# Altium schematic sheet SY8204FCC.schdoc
size 127 x 101 mm
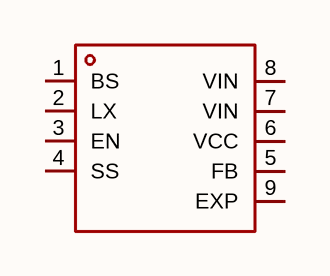
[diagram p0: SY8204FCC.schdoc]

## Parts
U?  sy8204fcc  [SOIC-8_L5.0-W4.0-P1.27-LS6.0-BL-EP2.0]  (value not drawn)

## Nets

Not connected (* = marked no-connect by the designer): U? 1(BS) 2(LX) 3(EN) 4(SS) 5(FB) 6(VCC) 7(VIN) 8(VIN) 9(EXP)

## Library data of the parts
U? = sy8204fcc: 功能类型:降压型;工作电压:4.5V~30V;输出电压:-;输出电流:4A;输出类型:可调;; Manufacturer: Silergy(矽力杰); AddInBom: yes; ModelId: d3dfb165ce8644e793b750cd6f375e75; ModelTransform: 192.913,236.22,0,0,0,0,0,0,0; Function: 降压型; Output Current: 4A; Frequency - Switching: 500kHz; Synchronous Rectifier: 是; Number of Outputs: 1; Topology: 降压式; Quiescent Current: 200uA; Switch tube (built-in/external): 内置; Output Type: 可调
